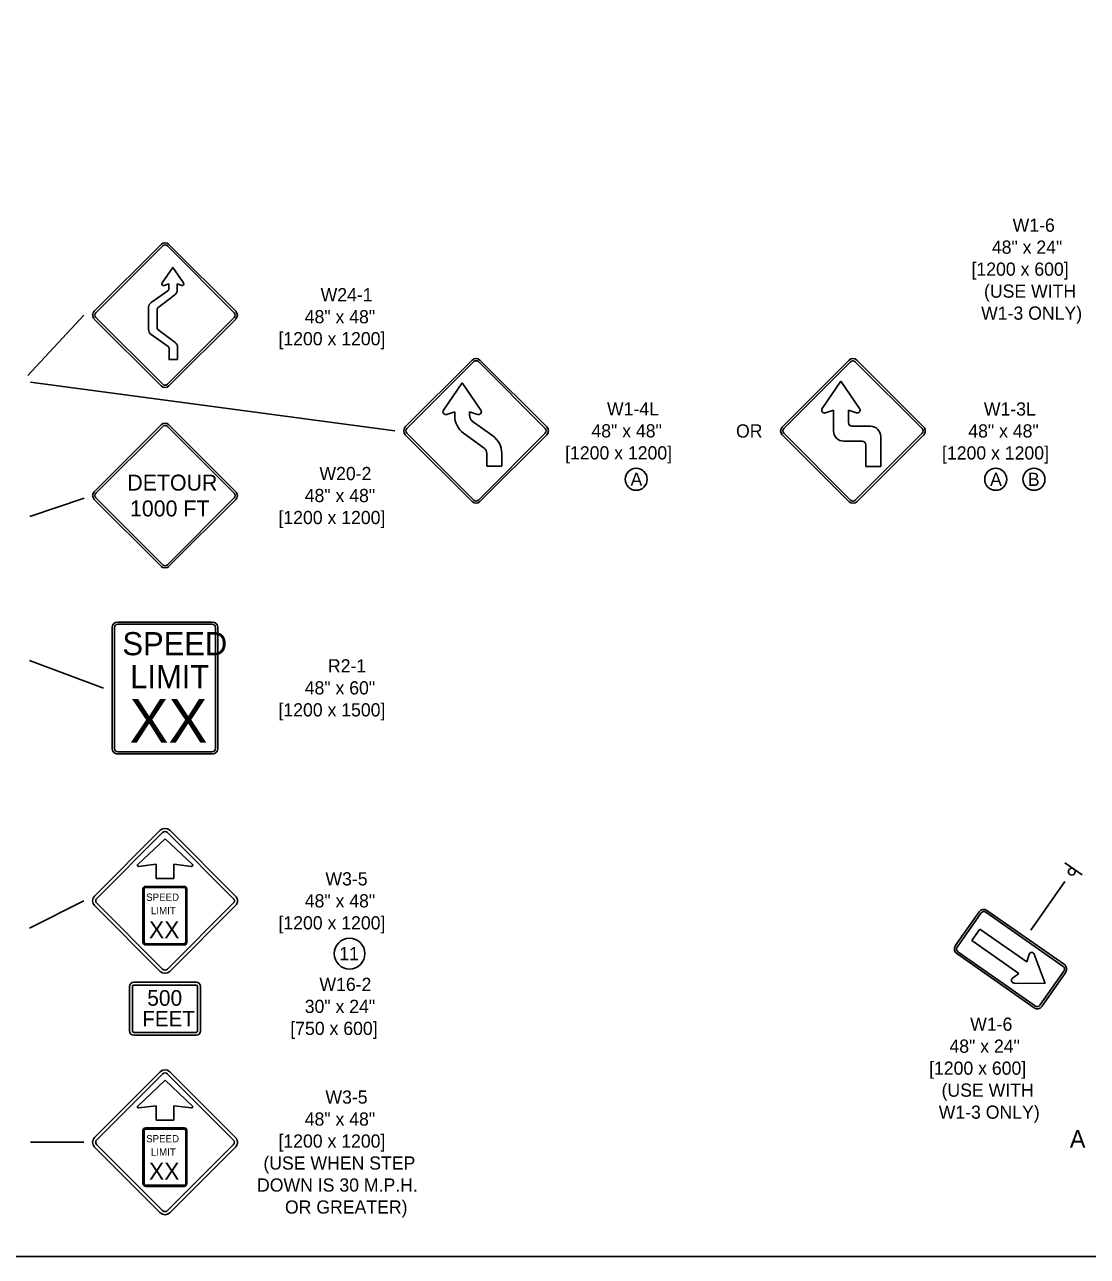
# Model space of a CAD drawing. Extents: x 49991.4 to 50021, y 49987.6 to 50011.4.
# Drawn here: x 50003.84 to 50008.68, y 49987.8 to 49993.4 of the extents above; entities that cross this region are included whole.
import ezdxf

# ---------------------------------------------------------------- set-up
doc = ezdxf.new("R2010")
doc.units = 0
for name, color, linetype in [('Level 1', 7, 'Continuous'), ('Level 2', 7, 'Continuous'), ('Level 3', 7, 'Continuous')]:
    doc.layers.add(name, color=color, linetype=linetype)

msp = doc.modelspace()

# ---------------------------------------------------------------- linework, layer by layer
at = {"layer": 'Level 1'}
for p, q in [((50004.1593, 49992.0963), (50004.4634, 49992.4003)), ((50004.1664, 49992.0892), (50004.4704, 49992.3933)), ((50004.4917, 49992.3933), (50004.7957, 49992.0892)), ((50004.4987, 49992.4003), (50004.8028, 49992.0963)), ((50004.517, 49992.2952), (50004.4684, 49992.2247)), ((50004.5655, 49992.2247), (50004.517, 49992.2952)), ((50004.4175, 49992.1361), (50004.4936, 49992.1893)), ((50004.4768, 49992.2135), (50004.4976, 49992.2202)), ((50004.4976, 49992.1969), (50004.4976, 49992.2202)), ((50004.5364, 49992.2202), (50004.5571, 49992.2135)), ((50004.5364, 49992.1921), (50004.5364, 49992.2202)), ((50004.4484, 49992.1115), (50004.5259, 49992.1708)), ((50004.406, 49992.0129), (50004.406, 49992.1142)), ((50004.4448, 49992.0212), (50004.4448, 49992.1042)), ((50004.4634, 49991.7569), (50004.1593, 49992.0609)), ((50004.4704, 49991.7639), (50004.1664, 49992.068)), ((50004.7957, 49992.068), (50004.4917, 49991.7639)), ((50004.8028, 49992.0609), (50004.4987, 49991.7569)), ((50004.4955, 49991.9357), (50004.4173, 49991.991)), ((50004.4485, 49992.0139), (50004.5274, 49991.9545)), ((50004.4993, 49991.8767), (50004.4993, 49991.9282)), ((50004.5381, 49991.8767), (50004.5381, 49991.9331)), ((50004.5381, 49991.8767), (50004.4993, 49991.8767)), ((50005.8778, 49991.874), (50005.5737, 49991.57)), ((50005.8849, 49991.867), (50005.5808, 49991.5629)), ((50006.2101, 49991.5629), (50005.9061, 49991.867)), ((50006.2172, 49991.57), (50005.9131, 49991.874)), ((50007.5919, 49991.8736), (50007.2878, 49991.5696)), ((50007.5989, 49991.8666), (50007.2949, 49991.5625)), ((50007.9242, 49991.5625), (50007.6202, 49991.8666)), ((50007.9313, 49991.5696), (50007.6272, 49991.8736)), ((50005.7472, 49991.647), (50005.8324, 49991.7707)), ((50005.8324, 49991.7707), (50005.9174, 49991.647)), ((50007.4697, 49991.6539), (50007.5548, 49991.7776)), ((50007.5548, 49991.7776), (50007.6399, 49991.6539)), ((50005.7984, 49991.6391), (50005.7619, 49991.6273)), ((50005.7984, 49991.6203), (50005.7984, 49991.6391)), ((50005.9028, 49991.6273), (50005.8663, 49991.6391)), ((50005.8663, 49991.6391), (50005.8663, 49991.6203)), ((50007.5208, 49991.6461), (50007.4844, 49991.6343)), ((50007.5208, 49991.5524), (50007.5208, 49991.6461)), ((50007.6252, 49991.6343), (50007.5888, 49991.6461)), ((50007.5888, 49991.6461), (50007.5888, 49991.5896)), ((50004.4634, 49991.5798), (50004.1593, 49991.2758)), ((50004.4705, 49991.5728), (50004.1664, 49991.2687)), ((50004.7957, 49991.2687), (50004.4917, 49991.5728)), ((50004.8028, 49991.2758), (50004.4987, 49991.5798)), ((50005.8784, 49991.5966), (50005.972, 49991.5291)), ((50007.6049, 49991.5734), (50007.6887, 49991.5734)), ((50005.5737, 49991.5346), (50005.8778, 49991.2306)), ((50005.5808, 49991.5417), (50005.8849, 49991.2376)), ((50005.9323, 49991.4739), (50005.8387, 49991.5415)), ((50005.9061, 49991.2376), (50006.2101, 49991.5417)), ((50005.9131, 49991.2306), (50006.2172, 49991.5346)), ((50007.2878, 49991.5342), (50007.5919, 49991.2302)), ((50007.2949, 49991.5413), (50007.5989, 49991.2372)), ((50007.6202, 49991.2372), (50007.9242, 49991.5413)), ((50007.6272, 49991.2302), (50007.9313, 49991.5342)), ((50007.7356, 49991.5265), (50007.7356, 49991.3906)), ((50007.6515, 49991.5054), (50007.5677, 49991.5054)), ((50007.6677, 49991.3906), (50007.6677, 49991.4893)), ((50005.9444, 49991.3921), (50005.9444, 49991.4504)), ((50006.0123, 49991.4504), (50006.0123, 49991.3921)), ((50006.0123, 49991.3921), (50005.9444, 49991.3921)), ((50007.7356, 49991.3906), (50007.6677, 49991.3906)), ((50004.1593, 49991.2404), (50004.4634, 49990.9364)), ((50004.1664, 49991.2475), (50004.4705, 49990.9434)), ((50004.4917, 49990.9434), (50004.7957, 49991.2475)), ((50004.4987, 49990.9364), (50004.8028, 49991.2404)), ((50004.266, 49990.6831), (50004.696, 49990.6831)), ((50004.266, 49990.6731), (50004.696, 49990.6731)), ((50004.241, 49990.1081), (50004.241, 49990.6581)), ((50004.251, 49990.1081), (50004.251, 49990.6581)), ((50004.711, 49990.6581), (50004.711, 49990.1081)), ((50004.721, 49990.6581), (50004.721, 49990.1081)), ((50004.696, 49990.0931), (50004.266, 49990.0931)), ((50004.696, 49990.0831), (50004.266, 49990.0831)), ((50004.4596, 49989.7361), (50004.1603, 49989.4368)), ((50004.4697, 49989.726), (50004.1704, 49989.4267)), ((50004.4596, 49989.7361), (50004.4596, 49989.7361)), ((50004.4697, 49989.726), (50004.4697, 49989.726)), ((50004.7916, 49989.4267), (50004.4923, 49989.726)), ((50004.8017, 49989.4368), (50004.5024, 49989.7361)), ((50004.481, 49989.6976), (50004.3566, 49989.5804)), ((50004.6054, 49989.5804), (50004.481, 49989.6976)), ((50004.3607, 49989.5717), (50004.4407, 49989.5817)), ((50004.4407, 49989.5817), (50004.4407, 49989.5162)), ((50004.5213, 49989.5162), (50004.5213, 49989.5817)), ((50004.5213, 49989.5817), (50004.6013, 49989.5717)), ((50008.6524, 49989.5329), (50008.5738, 49989.588)), ((50004.4407, 49989.5162), (50004.5213, 49989.5162)), ((50004.3806, 49989.2273), (50004.3806, 49989.4687)), ((50004.3858, 49989.2273), (50004.3858, 49989.4687)), ((50004.3931, 49989.4811), (50004.5679, 49989.4811)), ((50004.3931, 49989.4759), (50004.5679, 49989.4759)), ((50004.4805, 49989.4811), (50004.4805, 49989.4811)), ((50004.5751, 49989.4687), (50004.5751, 49989.2273)), ((50004.5803, 49989.4687), (50004.5803, 49989.2273)), ((50004.1603, 49989.394), (50004.4596, 49989.0947)), ((50004.1704, 49989.4041), (50004.4697, 49989.1048)), ((50004.4923, 49989.1048), (50004.7916, 49989.4041)), ((50004.5024, 49989.0947), (50004.8017, 49989.394)), ((50008.0751, 49989.2102), (50008.1841, 49989.3658)), ((50008.0833, 49989.2044), (50008.1923, 49989.3601)), ((50008.2132, 49989.3638), (50008.5654, 49989.1172)), ((50008.2189, 49989.372), (50008.5712, 49989.1254)), ((50008.1504, 49989.2343), (50008.1872, 49989.2868)), ((50008.1872, 49989.2868), (50008.4004, 49989.1375)), ((50004.5679, 49989.2201), (50004.3931, 49989.2201)), ((50008.3491, 49989.0953), (50008.1504, 49989.2343)), ((50004.5679, 49989.2149), (50004.3931, 49989.2149)), ((50008.4335, 49988.9288), (50008.0813, 49989.1754)), ((50008.4393, 49988.9369), (50008.087, 49989.1835)), ((50008.4004, 49989.1375), (50008.411, 49989.1721)), ((50008.4341, 49989.1728), (50008.4836, 49989.0402)), ((50008.3349, 49989.0633), (50008.3637, 49989.085)), ((50008.3637, 49989.085), (50008.3491, 49989.0953)), ((50008.5691, 49989.0963), (50008.4601, 49988.9406)), ((50008.5773, 49989.0905), (50008.4683, 49988.9349)), ((50004.3197, 49989.0257), (50004.3197, 49988.8241)), ((50004.3331, 49988.8241), (50004.3331, 49989.0257)), ((50004.6221, 49989.0459), (50004.3399, 49989.0459)), ((50004.3399, 49989.0324), (50004.6221, 49989.0324)), ((50004.6288, 49989.0257), (50004.6288, 49988.8241)), ((50004.6423, 49988.8241), (50004.6423, 49989.0257)), ((50008.4836, 49989.0402), (50008.3421, 49989.0414)), ((50004.6221, 49988.8174), (50004.3399, 49988.8174)), ((50004.3399, 49988.8039), (50004.6221, 49988.8039)), ((50004.4596, 49988.6381), (50004.1603, 49988.3388)), ((50004.4697, 49988.628), (50004.1704, 49988.3287)), ((50004.481, 49988.5997), (50004.3566, 49988.4824)), ((50004.4596, 49988.6381), (50004.4596, 49988.6381)), ((50004.4697, 49988.628), (50004.4697, 49988.628)), ((50004.6054, 49988.4824), (50004.481, 49988.5997)), ((50004.7916, 49988.3287), (50004.4923, 49988.628)), ((50004.8017, 49988.3388), (50004.5024, 49988.6381)), ((50004.3607, 49988.4737), (50004.4407, 49988.4837)), ((50004.4407, 49988.4837), (50004.4407, 49988.4182)), ((50004.5213, 49988.4182), (50004.5213, 49988.4837)), ((50004.5213, 49988.4837), (50004.6013, 49988.4737)), ((50004.3931, 49988.3831), (50004.5679, 49988.3831)), ((50004.3931, 49988.3779), (50004.5679, 49988.3779)), ((50004.4407, 49988.4182), (50004.5213, 49988.4182)), ((50004.4805, 49988.3831), (50004.4805, 49988.3831)), ((50004.3806, 49988.1294), (50004.3806, 49988.3707)), ((50004.3858, 49988.1294), (50004.3858, 49988.3707)), ((50004.5751, 49988.3707), (50004.5751, 49988.1294)), ((50004.5803, 49988.3707), (50004.5803, 49988.1294)), ((50004.1603, 49988.296), (50004.4596, 49987.9967)), ((50004.1704, 49988.3061), (50004.4697, 49988.0068)), ((50004.4923, 49988.0068), (50004.7916, 49988.3061)), ((50004.5024, 49987.9967), (50004.8017, 49988.296)), ((50004.5679, 49988.1221), (50004.3931, 49988.1221)), ((50004.5679, 49988.1169), (50004.3931, 49988.1169))]:
    msp.add_line(p, q, dxfattribs=at)
msp.add_lwpolyline([(49999.3835, 49998.9992), (50016.7501, 49998.9992), (50016.7501, 49987.7988), (49999.3835, 49987.7988)], close=True, dxfattribs=at)
for points in [[(50004.4684, 49992.2247), (50004.517, 49992.2952), (50004.5655, 49992.2247)], [(50004.4175, 49992.1361), (50004.4936, 49992.1893)], [(50004.4976, 49992.1969), (50004.4976, 49992.2202), (50004.4768, 49992.2135)], [(50004.5571, 49992.2135), (50004.5364, 49992.2202), (50004.5364, 49992.1921)], [(50004.5259, 49992.1708), (50004.4484, 49992.1115)], [(50004.406, 49992.0129), (50004.406, 49992.1142)], [(50004.4448, 49992.1042), (50004.4448, 49992.0212)], [(50004.4955, 49991.9357), (50004.4173, 49991.991)], [(50004.4485, 49992.0139), (50004.5274, 49991.9545)], [(50004.5381, 49991.8767), (50004.4993, 49991.8767), (50004.4993, 49991.9282)], [(50004.5381, 49991.9331), (50004.5381, 49991.8767)]]:
    msp.add_lwpolyline(points, dxfattribs=at)
msp.add_circle((50008.6044, 49989.548), 0.0152, dxfattribs=at)
for centre, radius, start, end in [((50004.481, 49992.3827), 0.025, 45, 135), ((50004.481, 49992.3827), 0.015, 45, 135), ((50004.4745, 49992.2206), 0.00738, 145.4806, 287.9582), ((50004.4745, 49992.2206), 0.00738, 145.4806, 287.9582), ((50004.4884, 49992.1969), 0.00918, 304.9427, 360), ((50004.4884, 49992.1969), 0.00918, 304.9427, 360), ((50004.5096, 49992.1921), 0.0267, 307.453, 0), ((50004.5096, 49992.1921), 0.0267, 307.453, 0), ((50004.5594, 49992.2206), 0.00738, 252.0418, 34.5194), ((50004.5594, 49992.2206), 0.00738, 252.0418, 34.5194), ((50004.4328, 49992.1142), 0.0267, 124.9427, 180), ((50004.4328, 49992.1142), 0.0267, 124.9427, 180), ((50004.1769, 49992.0787), 0.025, 134.9998, 225), ((50004.1769, 49992.0787), 0.015, 134.9998, 225), ((50004.454, 49992.1042), 0.00918, 127.453, 180), ((50004.454, 49992.1042), 0.00918, 127.453, 180), ((50004.785, 49992.0787), 0.015, 315, 45), ((50004.785, 49992.0787), 0.025, 315, 45), ((50004.454, 49992.0212), 0.00918, 180, 233.0725), ((50004.454, 49992.0212), 0.00918, 180, 233.0725), ((50004.4328, 49992.0129), 0.0267, 180, 234.7188), ((50004.4328, 49992.0129), 0.0267, 180, 234.7188), ((50004.4901, 49991.9282), 0.00918, 0, 54.7188), ((50004.4901, 49991.9282), 0.00918, 0, 54.7188), ((50004.5114, 49991.9331), 0.0267, 0, 53.0725), ((50004.5114, 49991.9331), 0.0267, 0, 53.0725), ((50005.8956, 49991.8564), 0.025, 45, 135), ((50005.8956, 49991.8564), 0.015, 45, 135), ((50007.6096, 49991.856), 0.025, 45, 135), ((50007.6096, 49991.856), 0.015, 45, 135), ((50004.481, 49991.7746), 0.025, 225.0004, 315), ((50004.481, 49991.7746), 0.015, 225.0004, 315), ((50005.758, 49991.6397), 0.0129, 145.4806, 287.9582), ((50005.9069, 49991.6397), 0.0129, 252.0418, 34.5194), ((50007.4804, 49991.6466), 0.0129, 145.4806, 287.9582), ((50007.6292, 49991.6466), 0.0129, 252.0418, 34.5194), ((50004.481, 49991.5621), 0.025, 45, 135), ((50004.481, 49991.5621), 0.015, 45, 135), ((50005.5915, 49991.5524), 0.025, 135, 225), ((50005.8956, 49991.6203), 0.0971, 180, 234.2028), ((50005.8956, 49991.6203), 0.0291, 180, 234.2028), ((50006.1996, 49991.5524), 0.025, 315, 45.0002), ((50007.3055, 49991.552), 0.025, 135, 225), ((50007.605, 49991.5896), 0.0162, 180, 270), ((50007.6887, 49991.5265), 0.0469, 0, 90), ((50007.9136, 49991.552), 0.025, 315, 45.0002), ((50005.5915, 49991.5524), 0.015, 135, 225), ((50005.9154, 49991.4504), 0.0971, 0, 54.2028), ((50006.1996, 49991.5524), 0.015, 315, 45.0002), ((50007.3055, 49991.552), 0.015, 135, 225), ((50007.5678, 49991.5524), 0.0469, 180, 270), ((50007.9136, 49991.552), 0.015, 315, 45.0002), ((50005.9154, 49991.4504), 0.0291, 0, 54.2026), ((50007.6515, 49991.4893), 0.0162, 0, 90), ((50004.1769, 49991.2581), 0.025, 135, 225), ((50004.1769, 49991.2581), 0.015, 135, 225), ((50004.785, 49991.2581), 0.015, 315, 45.0002), ((50004.785, 49991.2581), 0.025, 315, 45.0002), ((50005.8956, 49991.2483), 0.015, 225, 314.9996), ((50007.6096, 49991.2479), 0.015, 225, 314.9996), ((50005.8956, 49991.2483), 0.025, 225, 314.9996), ((50007.6096, 49991.2479), 0.025, 225, 314.9996), ((50004.481, 49990.954), 0.025, 225, 314.9996), ((50004.481, 49990.954), 0.015, 225, 314.9996), ((50004.2659, 49990.658), 0.025, 90, 180), ((50004.2659, 49990.658), 0.015, 90, 180), ((50004.6959, 49990.658), 0.025, 0, 90), ((50004.6959, 49990.658), 0.015, 0, 90), ((50004.2659, 49990.108), 0.025, 180, 270), ((50004.2659, 49990.108), 0.015, 180, 270), ((50004.6959, 49990.108), 0.025, 270, 0), ((50004.6959, 49990.108), 0.015, 270, 0), ((50004.481, 49989.7147), 0.0302, 45.0001, 134.9999), ((50004.481, 49989.7147), 0.016, 45.0001, 134.9999), ((50004.3601, 49989.5767), 0.00508, 134.6287, 275.8295), ((50004.6018, 49989.5767), 0.00509, 264.3826, 45.1649), ((50004.3931, 49989.4687), 0.0125, 90, 180), ((50004.3931, 49989.4687), 0.00728, 90, 180), ((50004.5679, 49989.4687), 0.0125, 360, 90), ((50004.5679, 49989.4687), 0.00728, 360, 90), ((50004.1817, 49989.4154), 0.0302, 134.9999, 225.0001), ((50004.1817, 49989.4154), 0.016, 134.9999, 225.0001), ((50004.7803, 49989.4154), 0.016, 314.9999, 45.0001), ((50004.7803, 49989.4154), 0.0302, 314.9999, 45.0001), ((50008.2046, 49989.3515), 0.025, 55.0057, 145.0057), ((50008.2046, 49989.3515), 0.015, 55.0057, 145.0057), ((50004.3931, 49989.2273), 0.0125, 180, 270), ((50004.3931, 49989.2273), 0.00728, 180, 270), ((50004.5679, 49989.2273), 0.00728, 270, 360), ((50004.5679, 49989.2273), 0.0125, 270, 360), ((50008.0956, 49989.1958), 0.025, 145.0057, 235.0057), ((50008.0956, 49989.1958), 0.015, 145.0057, 235.0057), ((50008.4227, 49989.1685), 0.0122, 20.4863, 162.9639), ((50004.481, 49989.1161), 0.016, 225.0001, 314.9999), ((50008.5568, 49989.1049), 0.015, 325.0057, 55.0057), ((50008.5568, 49989.1049), 0.025, 325.0057, 55.0057), ((50004.481, 49989.1161), 0.0302, 225.0001, 314.9999), ((50008.3422, 49989.0536), 0.0122, 127.0475, 269.5251), ((50004.3399, 49989.0257), 0.0202, 90, 180), ((50004.3399, 49989.0257), 0.00672, 90, 180), ((50004.6221, 49989.0257), 0.0202, 0, 90), ((50004.6221, 49989.0257), 0.00672, 0, 90), ((50008.4479, 49988.9492), 0.015, 235.0057, 325.0057), ((50008.4479, 49988.9492), 0.025, 235.0057, 325.0057), ((50004.3399, 49988.8241), 0.0202, 180, 270), ((50004.3399, 49988.8241), 0.00672, 180, 270), ((50004.6221, 49988.8241), 0.00672, 270, 360), ((50004.6221, 49988.8241), 0.0202, 270, 360), ((50004.481, 49988.6167), 0.0302, 45.0001, 134.9999), ((50004.481, 49988.6167), 0.016, 45.0001, 134.9999), ((50004.3601, 49988.4787), 0.00508, 134.6287, 275.8295), ((50004.6018, 49988.4787), 0.00509, 264.3826, 45.1649), ((50004.3931, 49988.3707), 0.0125, 90, 180), ((50004.3931, 49988.3707), 0.00728, 90, 180), ((50004.5679, 49988.3707), 0.0125, 360, 90), ((50004.5679, 49988.3707), 0.00728, 360, 90), ((50004.1817, 49988.3174), 0.0302, 134.9999, 225.0001), ((50004.1817, 49988.3174), 0.016, 134.9999, 225.0001), ((50004.7803, 49988.3174), 0.016, 314.9999, 45.0001), ((50004.7803, 49988.3174), 0.0302, 314.9999, 45.0001), ((50004.3931, 49988.1294), 0.0125, 180, 270), ((50004.3931, 49988.1294), 0.00728, 180, 270), ((50004.5679, 49988.1294), 0.00728, 270, 360), ((50004.5679, 49988.1294), 0.0125, 270, 360), ((50004.481, 49988.0181), 0.0302, 225.0001, 314.9999), ((50004.481, 49988.0181), 0.016, 225.0001, 314.9999)]:
    msp.add_arc(centre, radius, start, end, dxfattribs=at)
at = {"layer": 'Level 2'}
for centre, radius in [((50006.6238, 49991.3324), 0.05), ((50008.259, 49991.332), 0.05), ((50008.4328, 49991.332), 0.05), ((50005.3202, 49989.1754), 0.07)]:
    msp.add_circle(centre, radius, dxfattribs=at)
at = {"layer": 'Level 3'}
for p, q in [((50003.8564, 49991.8033), (50004.1119, 49992.0787)), ((50003.8687, 49991.7744), (50005.5265, 49991.5524)), ((50003.8666, 49991.1623), (50004.1136, 49991.2465)), ((50003.8653, 49990.5082), (50004.201, 49990.3831)), ((50008.5727, 49989.5027), (50008.418, 49989.2815)), ((50003.8653, 49989.2906), (50004.1115, 49989.4154)), ((50003.8687, 49988.3174), (50004.1115, 49988.3174))]:
    msp.add_line(p, q, dxfattribs=at)

# ---------------------------------------------------------------- texts
at = {"layer": 'Level 1'}
for s, height, p in [('DETOUR', 0.0725, (50004.3097, 49991.2808)), ('1000 FT', 0.0725, (50004.3217, 49991.1633)), ('SPEED', 0.03301, (50004.3952, 49989.4154)), ('LIMIT', 0.03301, (50004.417, 49989.3544)), ('XX', 0.07775, (50004.408, 49989.245)), ('SPEED', 0.03301, (50004.3952, 49988.3174)), ('LIMIT', 0.03301, (50004.417, 49988.2564)), ('XX', 0.07775, (50004.408, 49988.147))]:
    msp.add_text(s, height=height, rotation=360, dxfattribs=at).set_placement(p)
for s, height, p in [('SPEED', 0.10512, (50004.2872, 49990.5321)), ('LIMIT', 0.10512, (50004.3226, 49990.382)), ('XX', 0.1989, (50004.3194, 49990.1347)), ('500', 0.07124, (50004.4001, 49988.9383)), ('FEET', 0.06989, (50004.3777, 49988.8443))]:
    msp.add_text(s, height=height, dxfattribs=at).set_placement(p)
at = {"layer": 'Level 2'}
for s, height, p in [('W1-6', 0.06, (50008.3357, 49992.4577)), ('48" x 24"', 0.06, (50008.2413, 49992.3577)), ('[1200 x 600]', 0.06, (50008.1488, 49992.2577)), ('W24-1', 0.06, (50005.1886, 49992.1413)), ('(USE WITH', 0.06, (50008.2055, 49992.1577)), ('48" x 48"', 0.06, (50005.1163, 49992.0413)), ('W1-3 ONLY)', 0.06, (50008.1925, 49992.0577)), ('[1200 x 1200]', 0.06, (50004.9969, 49991.9413)), ('W1-4L', 0.06, (50006.4909, 49991.6224)), ('W1-3L', 0.06, (50008.2049, 49991.622)), ('48" x 48"', 0.06, (50006.4201, 49991.5224)), ('OR', 0.06, (50007.0777, 49991.522)), ('48" x 48"', 0.06, (50008.1341, 49991.522)), ('[1200 x 1200]', 0.06, (50006.3006, 49991.4224)), ('[1200 x 1200]', 0.06, (50008.0146, 49991.422)), ('W20-2', 0.06, (50005.1832, 49991.3283)), ('A', 0.06, (50006.598, 49991.3024)), ('A', 0.06, (50008.2332, 49991.302)), ('B', 0.06, (50008.405, 49991.302)), ('48" x 48"', 0.06, (50005.1163, 49991.2283)), ('[1200 x 1200]', 0.06, (50004.9969, 49991.1283)), ('R2-1', 0.06, (50005.2219, 49990.4538)), ('48" x 60"', 0.06, (50005.1163, 49990.3538)), ('[1200 x 1500]', 0.06, (50004.9969, 49990.2538)), ('W3-5', 0.06, (50005.2105, 49989.4854)), ('48" x 48"', 0.06, (50005.1165, 49989.3854)), ('[1200 x 1200]', 0.06, (50004.997, 49989.2854)), ('11', 0.06, (50005.2735, 49989.1454)), ('W16-2', 0.05999, (50005.1832, 49989.0055)), ('30" x 24"', 0.05999, (50005.1164, 49988.9055)), ('W1-6', 0.06, (50008.1427, 49988.8246)), ('[750 x 600]', 0.059993, (50005.0508, 49988.8055)), ('48" x 24"', 0.06, (50008.0483, 49988.7246)), ('[1200 x 600]', 0.06, (50007.9558, 49988.6246)), ('W3-5', 0.06, (50005.2104, 49988.4932)), ('(USE WITH', 0.06, (50008.0125, 49988.5246)), ('W1-3 ONLY)', 0.06, (50007.9996, 49988.4246)), ('48" x 48"', 0.06, (50005.1163, 49988.3932)), ('[1200 x 1200]', 0.06, (50004.9969, 49988.2932)), ('A', 0.08, (50008.5957, 49988.2927)), ('(USE WHEN STEP', 0.06, (50004.9283, 49988.1932)), ('DOWN IS 30 M.P.H.', 0.06, (50004.8994, 49988.0932)), ('OR GREATER)', 0.06, (50005.0265, 49987.9932))]:
    msp.add_text(s, height=height, dxfattribs=at).set_placement(p)

doc.saveas('drawing.dxf')
